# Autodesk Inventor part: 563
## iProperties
Author: Administrator
Shininess: 64.0
Angle Display Precision: 2
Document Length Units: 11272
Document Angle Units: 11286
Document Time Units: 11279
Document Mass Units: 11290
Document Length Units Precision: 3
Document Angle Units Precision: 2
Compacted: True
PropertySet Name: _Private Model Information
Created: 2002-03
Part Number: 563
Material: Stainless Steel, 440C
Document SubType Name: Modeling
Designer: Administrator
Control State: 0
Master: False
Checked Out: False
PropertySet Name: Design Tracking Control
Density: 0.0
Volumn: 0.0
Area: 0.0
PropertySet Name: Model Information
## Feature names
1. Revolution1
